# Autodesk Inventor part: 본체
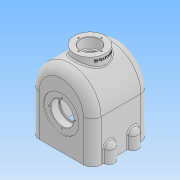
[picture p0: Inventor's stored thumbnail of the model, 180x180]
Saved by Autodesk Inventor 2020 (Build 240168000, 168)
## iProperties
Created: 2023-03
Part Number: 본체
Material: 일반
Document SubType Name: Modeling
Designer: user
Density: 1 g/cm^3
Appearance: 기본값
Author: user
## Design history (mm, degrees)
sketch "스케치1"
  geometry: L1 (70, -75)-(-70, -75); L2 (-70, -75)-(-70, 19); L3 (-70, 19)-(70, 19); L4 (70, 19)-(70, -75); L5 (70, -75)-(-70, 19); L6 (-70, -75)-(70, 19); A1 r 70 centre (0, 19) between (70, 19) and (-70, 19); 3 further points
  constraints: 12 end point, 4 midpoint, 2 parallel, 2 point on circle, 1 centre point, 1 horizontal, 1 perpendicular, 1 vertical alignment
  dimensions: "d0" = 140 distance of L2.end L3.end; "d1" = 94 distance of L1.end L2.end; "d2" = 75 distance from line of L1 point (0, 0)
extrude "돌출1" new body sketch "스케치1" stored distance "d3" = 130; taper "d4" = 0 deg
fillet "모깎기1" dims "d5" = 20
feature "쉘1" dims "d6" = 10
node "작업 평면1"
sketch "스케치2"
  geometry: C1 r 30 at (0, 0); 1 further point
  constraints: 1 centre point, 1 coincident
  dimensions: "d8" = 60 diameter of C1
extrude "돌출2" join sketch "스케치2" stored distance "d9" = 130; taper "d10" = 45 deg
sketch "스케치3"
  geometry: C1 r 40 at (0, 0); 1 further point
  constraints: 1 centre point, 1 coincident
  dimensions: "d11" = 80 diameter of C1
extrude "돌출3" cut sketch "스케치3" distance "d12" = 2; taper "d13" = 0 deg
sketch "스케치4"
  geometry: C1 r 40 at (0, 0) reference; C2 r 26 at (0, 0)
  constraints: 1 centre point, 1 coincident
  dimensions: "d14" = 52 diameter of C2
extrude "돌출4" cut sketch "스케치4" distance "d15" = 18; taper "d16" = 0 deg
sketch "스케치5"
  geometry: L1 (0, 0)-(0, 30); C1 r 40 at (0, 0) reference; 1 further point
  constraints: 2 end point, 1 coincident, 1 vertical
  dimensions: "d17" = 30 distance of L1.start L1.end
hole "구멍1" sketch "스케치5" at (0, 30) diameter "d18" = 3.242; stored, may be unused: countersink angle "d22" = 90 deg, drill point angle "d24" = 118 deg; dims "d19" = 8, "d20" = 8, "d21" = 4.4, "d23" = 10
sketch "스케치6"
  geometry: C1 r 26 at (0, 0) reference; C2 r 23 at (0, 0)
  constraints: 1 centre point, 1 coincident
  dimensions: "d28" = 46 diameter of C2
extrude "돌출5" cut sketch "스케치6" extent not by distance; stored distance "d29" = 18; taper "d30" = 0 deg
sketch "스케치7"
  geometry: L1 (120, -110)-(120, -20) reference; L2 (120, -26)-(120, -50); L3 (120, -110)-(120, -20) reference; L4 (120, -80)-(120, -104); A1 r 12 centre (120, -38) between (120, -50) and (120, -26); A2 r 12 centre (120, -92) between (120, -104) and (120, -80); 4 further points
  constraints: 7 point on line, 4 end point, 4 point on circle, 2 centre point
  dimensions: "d31" = 24 diameter of A1; "d32" = 24 diameter of A2; "d33" = 54 distance of A2.centre A1.centre; "d34" = 27 vertical distance of point (50, -65) A1.centre (= 0.5 x d33)
extrude "돌출6" join sketch "스케치7" distance "d35" = 40; taper "d36" = 0 deg
fillet "모깎기2" dims "d37" = 12
sketch "스케치8"
  geometry: A1 r 12 centre (120, -92) between (120, -104) and (120, -80) reference; A2 r 12 centre (120, -38) between (120, -50) and (120, -26) reference; A3 r 12 centre (-20, -38) between (-20, -26) and (-20, -50) reference; A4 r 12 centre (-20, -92) between (-20, -80) and (-20, -104) reference; 5 further points
  constraints: 4 coincident
hole "구멍2" sketch "스케치8" at (-20, -38), (120, -92), (120, -38), (-20, -92) diameter "d38" = 10.106; stored, may be unused: countersink angle "d42" = 90 deg, drill point angle "d44" = 118 deg; dims "d39" = 24, "d40" = 8, "d41" = 4.4, "d43" = 26
node "작업 평면2"
sketch "스케치9"
  geometry: C1 r 35 at (-50, -65); 1 further point
  constraints: 1 centre point, 1 coincident
  dimensions: "d46" = 70 diameter of C1
extrude "돌출7" join sketch "스케치9" stored distance "d47" = 40; taper "d48" = 0 deg
sketch "스케치10"
  geometry: C1 r 35 at (0, 0) reference; 2 further points
  constraints: 1 coincident
hole "구멍3" sketch "스케치10" at (0, 0) diameter "d49" = 34; stored, may be unused: countersink angle "d53" = 90 deg, drill point angle "d55" = 0 deg; dims "d50" = 24, "d51" = 43, "d52" = 22, "d54" = 26
sketch "스케치11"
  geometry: L1 (0, 0)-(0, 26); C1 r 35 at (0, 0) reference; 1 further point
  constraints: 2 end point, 1 coincident, 1 vertical
  dimensions: "d56" = 26 distance of L1.start L1.end
hole "구멍4" sketch "스케치11" at (0, 26) diameter "d57" = 3.242; stored, may be unused: countersink angle "d61" = 90 deg, drill point angle "d63" = 118 deg; dims "d58" = 8, "d59" = 43, "d60" = 22, "d62" = 10
fillet "모깎기3" dims "d67" = 1
fillet "모깎기4" dims "d68" = 3
chamfer "모따기1" distance "d69" = 1; stored, may be unused: second distance "d70" = 2, angle "d71" = 45 deg
node "작업 평면3"
sketch "스케치12"
  geometry: L1 (103, -35)-(103, 35) reference; 2 further points
  constraints: 1 horizontal alignment, 1 other
  dimensions: "d73" = 8 distance from line of L1 point (95, 0)
feature "엠보싱1" sketch "스케치12" dims "d0" = 140, "d1" = 94, "d2" = 75, "d74" = 0.5, "d75" = 0
node "솔리드1"
mirror "미러1"
pattern_circular "원형 패턴1" dims angle "d26" = 360 deg
mirror "미러2"
mirror "미러3"
pattern_circular "원형 패턴2" dims angle "d65" = 360 deg
feature "A9D066F2-1C7D-4E18-AEED-F7BC21143FA4" dims "d18" = 3.242, "d19" = 8, "d20" = 8, "d21" = 4.4, "d22" = 90 deg, "d23" = 10, "d24" = 118 deg
other parameters: "d7" = -22, "d45" = -178
